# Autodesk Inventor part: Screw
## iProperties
Shininess: 77.0
Length Units: 11269
Angle Units: 11279
Time Units: 11290
Mass Units: 11283
Length Display Precision: 3
Angle Display Precision: 2
Created: 2002-01
Part Number: Screw
Document SubType Name: Modeling
Designer: ***
Density: 0.0
Volumn: 0.0
Area: 0.0
PropertySet Name: Model Information
Control State: 0
Master: False
Checked Out: False
Author: ***
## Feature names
1. Revolution1
2. Extrusion2
3. Extrusion3
4. Chamfer1
